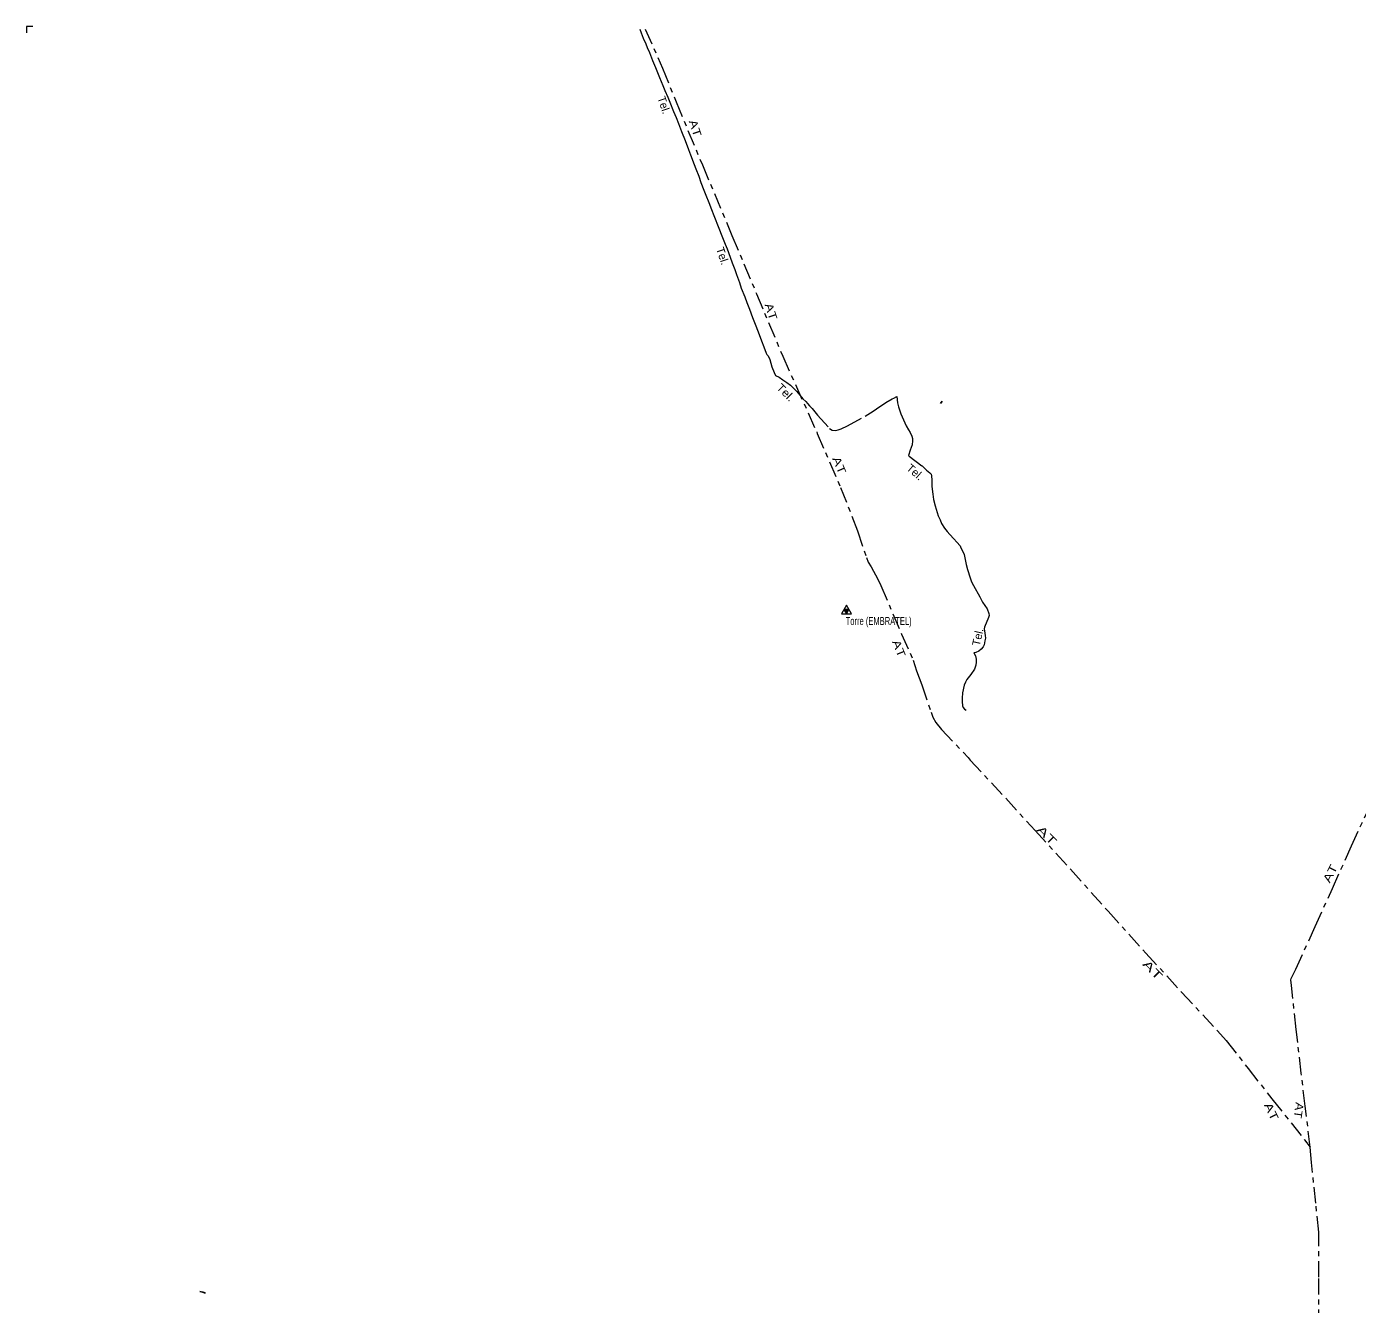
# Model space of a CAD drawing. Extents: x 552.5 to 605.3, y 7843.5 to 7899.1.
# Drawn here: x 552.62 to 579.23, y 7873.54 to 7899.08 of the extents above; entities that cross this region are included whole.
import ezdxf
from ezdxf.enums import TextEntityAlignment as Align

# ---------------------------------------------------------------- set-up
doc = ezdxf.new("R2010")
doc.units = 0
doc.header["$LTSCALE"] = 0.064
doc.linetypes.add('DOT_DASHED', pattern=[7.7, 5, -1.2, 0.3, -1.2])
for name, color, linetype, lineweight in [('24', 7, 'Continuous', 25), ('3', 7, 'Continuous', 13), ('56', 7, 'DOT_DASHED', 13), ('57', 7, 'DOT_DASHED', 13), ('63', 7, 'Continuous', 13)]:
    doc.layers.add(name, color=color, linetype=linetype, lineweight=lineweight)
doc.layers.add('61', color=7, linetype='Continuous')

msp = doc.modelspace()

# ---------------------------------------------------------------- hatches: boundary and pattern name
at = {"layer": '3'}
msp.add_hatch(color=256, dxfattribs=at).paths.add_polyline_path([(569.0603, 7887.4284), (568.9603, 7887.4284), (569.0103, 7887.3424)])

# ---------------------------------------------------------------- linework, layer by layer
at = {"layer": '24'}
msp.add_line((570.8909, 7891.5503), (570.9283, 7891.5915), dxfattribs=at)
msp.add_lwpolyline([(556.0827, 7873.7949), (556.14, 7873.7771), (556.1973, 7873.7593)], dxfattribs=at)
at = {"layer": '3'}
for points in [[(569.1103, 7887.3424), (569.0103, 7887.5154), (568.9103, 7887.3424)], [(569.0603, 7887.4284), (568.9603, 7887.4284), (569.0103, 7887.3424)]]:
    msp.add_lwpolyline(points, close=True, dxfattribs=at)
at = {"layer": '56'}
for points in [[(564.989, 7899.0325), (565.3346, 7898.2549), (565.6051, 7897.5799), (566.1315, 7896.3179), (566.7231, 7894.9092), (567.2144, 7893.7386), (567.7383, 7892.4928), (568.4301, 7890.9512), (568.8963, 7889.8708), (569.2322, 7889.001), (569.4102, 7888.4696), (569.4478, 7888.3743), (569.5079, 7888.2791), (569.6433, 7888.0359), (569.6985, 7887.9106), (570.1146, 7886.938), (570.3477, 7886.4166), (570.3828, 7886.3089), (570.4128, 7886.2061), (570.5198, 7885.9247), (570.7034, 7885.3736), (570.7423, 7885.2783), (570.7988, 7885.1687), (570.9154, 7885.0274), (571.4469, 7884.4708), (571.488, 7884.4198), (572.1991, 7883.6561), (572.7834, 7883.0125), (573.4928, 7882.2356), (574.2433, 7881.3978), (574.9988, 7880.56), (575.7131, 7879.7799), (576.4324, 7879.0063), (576.6069, 7878.8137), (577.043, 7878.2524), (577.5187, 7877.6484), (578.1738, 7876.8238), (578.2841, 7876.6789)], [(578.2841, 7876.6789), (578.187, 7877.5019), (578.1063, 7878.1586), (578.0076, 7879.0326), (577.9105, 7879.9099), (577.8989, 7880.0218), (577.9055, 7880.0515), (577.9977, 7880.2407), (578.3878, 7881.0933), (578.7285, 7881.8505), (579.112, 7882.7031), (579.4214, 7883.3779), (579.614, 7883.8157), (579.7983, 7884.2058), (580.0469, 7884.7852), (580.2375, 7885.2039), (580.2791, 7885.2377), (580.3811, 7885.3778), (580.4344, 7885.4505), (580.5505, 7885.5061), (581.046, 7885.8073), (581.6599, 7886.1826), (582.1701, 7886.4904), (582.7615, 7886.8475)], [(578.4476, 7866.9591), (578.4476, 7867.2281), (578.4457, 7868.1818), (578.4552, 7869.1732), (578.457, 7870.0894), (578.4664, 7871.0545), (578.4646, 7872.0271), (578.4627, 7873.1125), (578.457, 7874.0776), (578.4608, 7874.9824), (578.3968, 7875.5581), (578.3122, 7876.3708), (578.2841, 7876.6789)]]:
    msp.add_lwpolyline(points, dxfattribs=at)
at = {"layer": '57'}
for points in [[(564.8789, 7899.0329), (564.9071, 7898.9556), (564.9485, 7898.8547), (565, 7898.7377), (565.0302, 7898.663), (565.0716, 7898.5631), (565.1341, 7898.4077), (565.1937, 7898.2685), (565.2751, 7898.0682), (565.343, 7897.9043), (565.3834, 7897.8064), (565.4399, 7897.6722), (565.4802, 7897.5743), (565.5569, 7897.3857), (565.6063, 7897.2666), (565.6558, 7897.1476), (565.7173, 7896.9851), (565.79, 7896.8065), (565.8576, 7896.6279), (565.8969, 7896.518), (565.9686, 7896.3293), (566.0029, 7896.2385), (566.0594, 7896.0912), (566.1017, 7895.9671), (566.1633, 7895.8127), (566.1986, 7895.7158), (566.2632, 7895.5635), (566.3146, 7895.4283), (566.3631, 7895.3062), (566.4599, 7895.055), (566.5205, 7894.9006), (566.587, 7894.7331), (566.6244, 7894.6413), (566.6869, 7894.4769), (566.7303, 7894.3608), (566.7787, 7894.2266), (566.8161, 7894.1288), (566.8716, 7893.9663), (566.9099, 7893.8523), (566.9775, 7893.6808), (567.0229, 7893.5648), (567.0744, 7893.4316), (567.1359, 7893.2691), (567.2005, 7893.1037), (567.2671, 7892.9261), (567.3125, 7892.803), (567.3599, 7892.6819), (567.4103, 7892.5538), (567.4231, 7892.5253), (567.4444, 7892.499), (567.4816, 7892.4287), (567.5188, 7892.2838), (567.5644, 7892.168), (567.5936, 7892.1103), (567.6686, 7892.0722), (567.7411, 7892.0204), (567.8222, 7891.9703), (567.893, 7891.9133), (567.9414, 7891.8684), (568.0225, 7891.7856), (568.0795, 7891.7165), (568.1434, 7891.6423), (568.2021, 7891.5853), (568.2314, 7891.5473), (568.2763, 7891.5024), (568.3247, 7891.4454), (568.4352, 7891.3177), (568.6769, 7891.05), (568.7287, 7891.0138), (568.7908, 7891.0086), (568.8444, 7891.0224), (568.9082, 7891.0397), (569.036, 7891.1001), (569.3848, 7891.2935), (569.5453, 7891.3971), (569.611, 7891.4385), (569.8009, 7891.5646), (569.9252, 7891.6388), (569.9581, 7891.6565), (570.0219, 7891.6908), (570.0339, 7891.558), (570.0535, 7891.4785), (570.1024, 7891.3416), (570.2063, 7891.1044), (570.2515, 7891.0188), (570.2833, 7890.965), (570.3188, 7890.8965), (570.3322, 7890.8513), (570.3359, 7890.7987), (570.3237, 7890.7242), (570.2894, 7890.6166), (570.252, 7890.5091), (570.2669, 7890.4954), (570.5273, 7890.2994), (570.6108, 7890.2167), (570.6816, 7890.1615), (570.7037, 7890.1367), (570.7114, 7890.1037), (570.7225, 7890.016), (570.7177, 7889.8854)], [(570.7177, 7889.8854), (570.74, 7889.7356), (570.7544, 7889.6304), (570.7879, 7889.5013), (570.8468, 7889.299), (570.8835, 7889.2225), (570.9121, 7889.1476), (570.9743, 7889.0567), (571.0237, 7888.9898), (571.0811, 7888.9261), (571.1623, 7888.84), (571.2213, 7888.7747), (571.2834, 7888.7046), (571.2978, 7888.66), (571.3233, 7888.6153), (571.3631, 7888.5309), (571.3822, 7888.464), (571.4093, 7888.3269), (571.4348, 7888.2297), (571.4858, 7888.064), (571.5161, 7887.9843), (571.5512, 7887.911), (571.677, 7887.6831), (571.7344, 7887.5764), (571.8252, 7887.4425), (571.8603, 7887.3469), (571.8635, 7887.307), (571.8523, 7887.2704), (571.7727, 7887.0776), (571.7679, 7887.0393), (571.7727, 7886.9995), (571.787, 7886.9087), (571.7902, 7886.8529), (571.7806, 7886.8003), (571.7647, 7886.7254), (571.7456, 7886.684), (571.7057, 7886.633), (571.6579, 7886.5979), (571.5974, 7886.5692), (571.5626, 7886.5641), (571.5939, 7886.5038), (571.6074, 7886.4341), (571.6086, 7886.373), (571.5976, 7886.3143), (571.5707, 7886.2385), (571.5022, 7886.1297), (571.4228, 7886.0319), (571.391, 7885.9756), (571.369, 7885.9157), (571.336, 7885.7653), (571.3262, 7885.659), (571.3233, 7885.5872), (571.3311, 7885.5049), (571.3433, 7885.4719), (571.3727, 7885.4352), (571.406, 7885.4144)]]:
    msp.add_lwpolyline(points, dxfattribs=at)
at = {"layer": '63'}
msp.add_lwpolyline([(552.7429, 7899.0832), (552.6197, 7899.0832), (552.6197, 7898.9618)], dxfattribs=at)

# ---------------------------------------------------------------- texts
at = {"layer": '61'}
for rotation, p in [(288.435, (565.28735, 7897.49095)), (288.435, (566.45945, 7894.47255)), (319.399, (570.33304, 7890.11653)), (77.471, (571.71631, 7886.8626))]:
    msp.add_text('Tel.', height=0.16, rotation=rotation, dxfattribs=at).set_placement(p, align=Align.CENTER)
for s, rotation, width, p in [('AT', 288.435, 1.25, (565.91223, 7897.0278)), ('AT', 288.435, 1.25, (567.42923, 7893.3613)), ('Tel.', 315, 1.1, (567.73943, 7891.71367)), ('AT', 293.199, 1.3, (568.79492, 7890.28111)), ('AT', 291.801, 1.3, (569.98686, 7886.61936)), ('AT', 315, 1.65, (572.96188, 7882.85622)), ('AT', 63.435, 1.35, (578.75699, 7882.11547)), ('AT', 314.061, 1.65, (575.07748, 7880.16588)), ('AT', 295.641, 1.35, (577.43675, 7877.35652)), ('AT', 261.87, 1.15, (577.97598, 7877.42746))]:
    msp.add_text(s, height=0.16, rotation=rotation, dxfattribs=dict(at, width=width)).set_placement(p, align=Align.CENTER)
at = {"layer": '61', "width": 0.65}
msp.add_text('Torre (EMBRATEL)', height=0.16, dxfattribs=at).set_placement((568.997, 7887.1193))

doc.saveas('drawing.dxf')
